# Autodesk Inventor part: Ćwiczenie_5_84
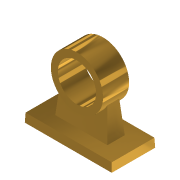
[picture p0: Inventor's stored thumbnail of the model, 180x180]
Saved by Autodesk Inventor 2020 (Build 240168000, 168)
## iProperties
Created: 2009-12
Part Number: Ćwiczenie_5_84
Document SubType Name: Modeling
Designer: F.Stasiak
Density: 8.47 g/cm^3
Material: Mosiądz, jasnożółty
Mass: 967.05 g
Surface Area: 271.696 cm^2
Volume: 114.173 cm^3
Appearance: Mosiądz — satynowy
Manager: www.cadconsulting.pl
Company: Fabian Stasiak CAD Consulting
Author: F.Stasiak
Subject: Zbiór ćwiczeń. Autodesk Inventor 2020. Kurs podstawowy
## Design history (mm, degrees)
sketch "Szkic1"
  geometry: L1 (-50, 25)-(50, 25); L2 (50, 25)-(50, -25); L3 (50, -25)-(-50, -25); L4 (-50, -25)-(-50, 25); 3 further points
  constraints: 8 end point, 2 midpoint, 2 parallel, 1 horizontal, 1 horizontal alignment, 1 perpendicular, 1 vertical alignment
  dimensions: "d0" = 100 distance of L2.end L3.end; "d1" = 50 distance of L3.end L1.start
extrude "Wyciągnięcie proste1" new body sketch "Szkic1" distance "d2" = 10; taper "d3" = -2.5 deg
sketch "Szkic2"
  geometry: L1 (-30, 10)-(30, 10); L2 (30, 10)-(30, -10); L3 (30, -10)-(-30, -10); L4 (-30, -10)-(-30, 10); L5 (-30, 10)-(30, -10); L6 (30, 10)-(-30, -10); 1 further point
  constraints: 12 end point, 2 midpoint, 2 parallel, 1 horizontal, 1 perpendicular
  dimensions: "d16" = 60 distance of L2.end L3.end; "d17" = 20 distance of L1.end L2.end
extrude "Wyciągnięcie proste2" join sketch "Szkic2" distance "d6" = 50; taper "d7" = -5 deg
sketch "Szkic3"
  geometry: C1 r 30 at (0, 60); 1 further point
  constraints: 1 centre point, 1 vertical alignment
  dimensions: "d9" = 60 diameter of C1; "d10" = 60 distance of C1.centre point (0, 0) (= d6 + d2)
extrude "Wyciągnięcie proste3" join sketch "Szkic3" stored distance "d11" = 30; taper "d12" = 0 deg
sketch "Szkic4"
  geometry: C1 r 30 at (0, 0) reference; C2 r 22 at (0, 0); 1 further point
  constraints: 1 centre point, 1 coincident
  dimensions: "d13" = 8 radial gap between concentric circles of C1 C2
extrude "Wyciągnięcie proste4" cut sketch "Szkic4" extent not by distance; stored distance "d14" = 30; taper "d15" = 0 deg
node "Bryła1"
